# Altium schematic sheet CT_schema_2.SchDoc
size 451 x 443 mm
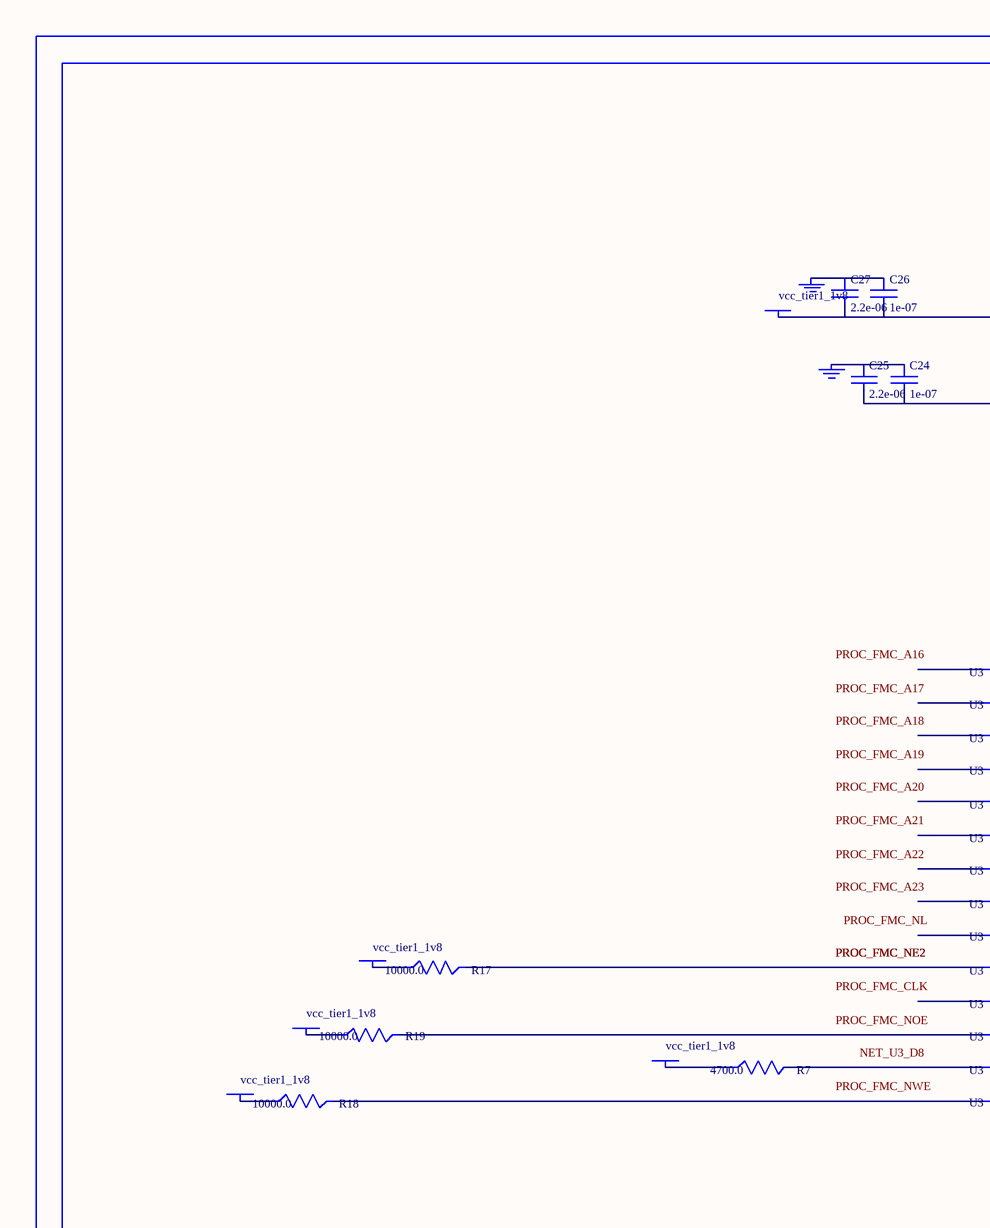
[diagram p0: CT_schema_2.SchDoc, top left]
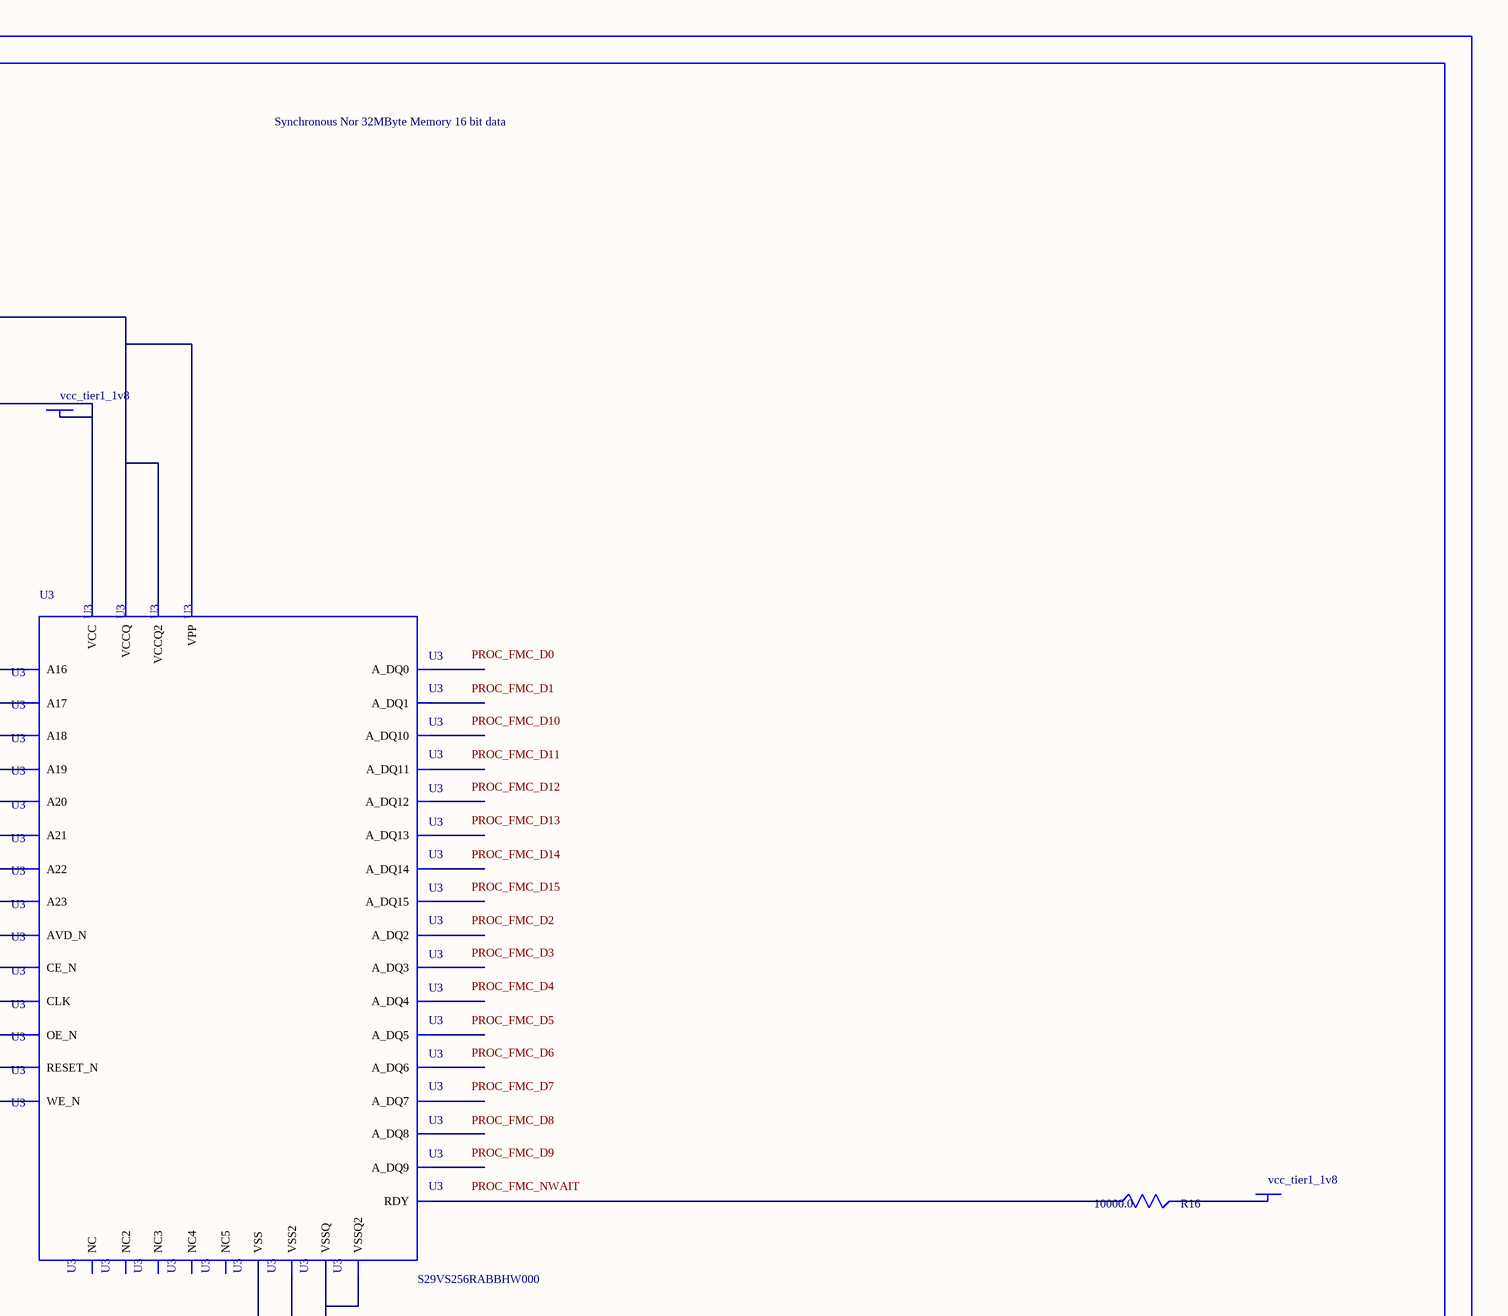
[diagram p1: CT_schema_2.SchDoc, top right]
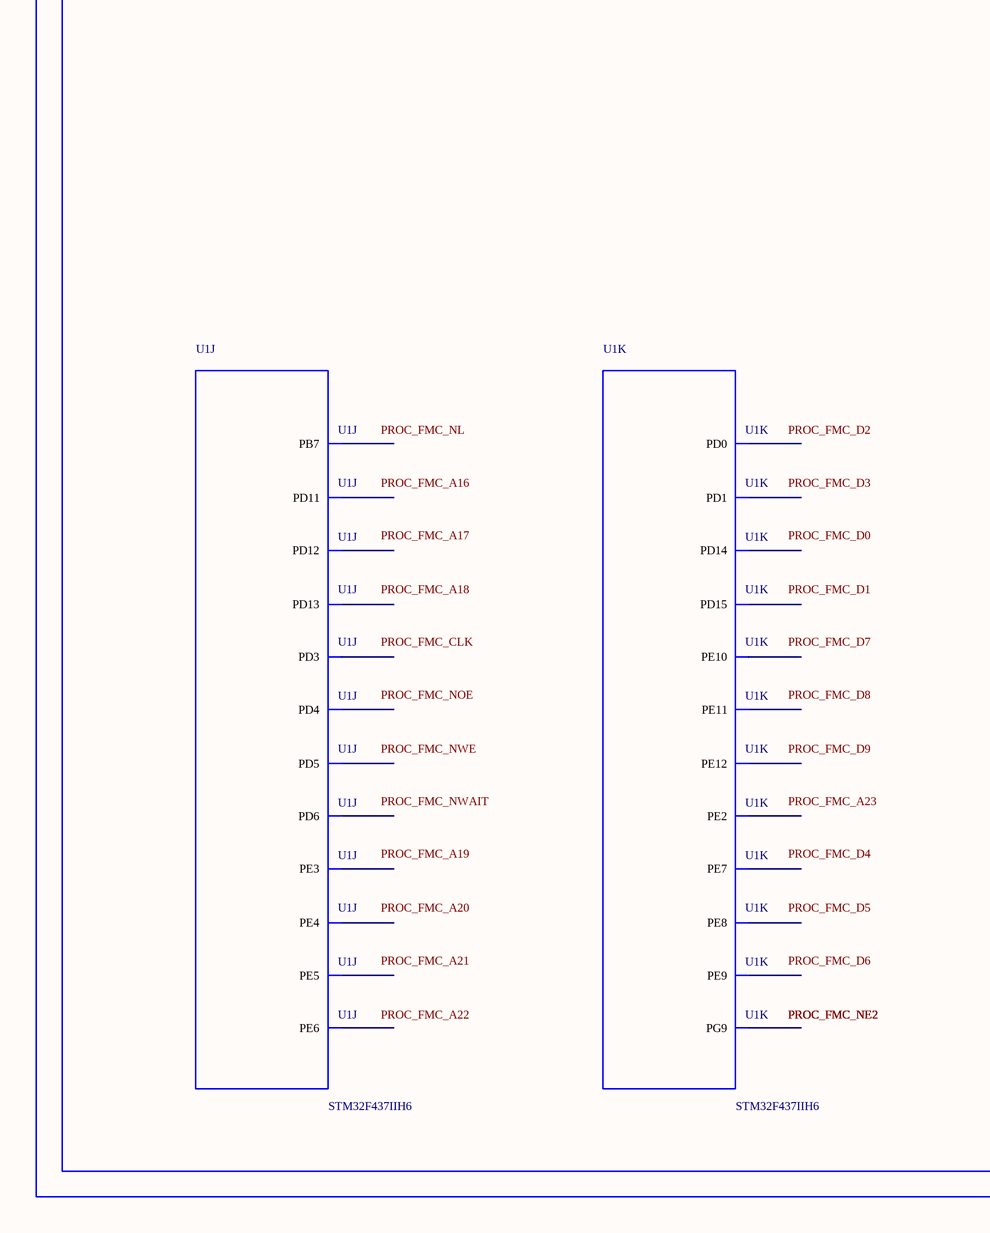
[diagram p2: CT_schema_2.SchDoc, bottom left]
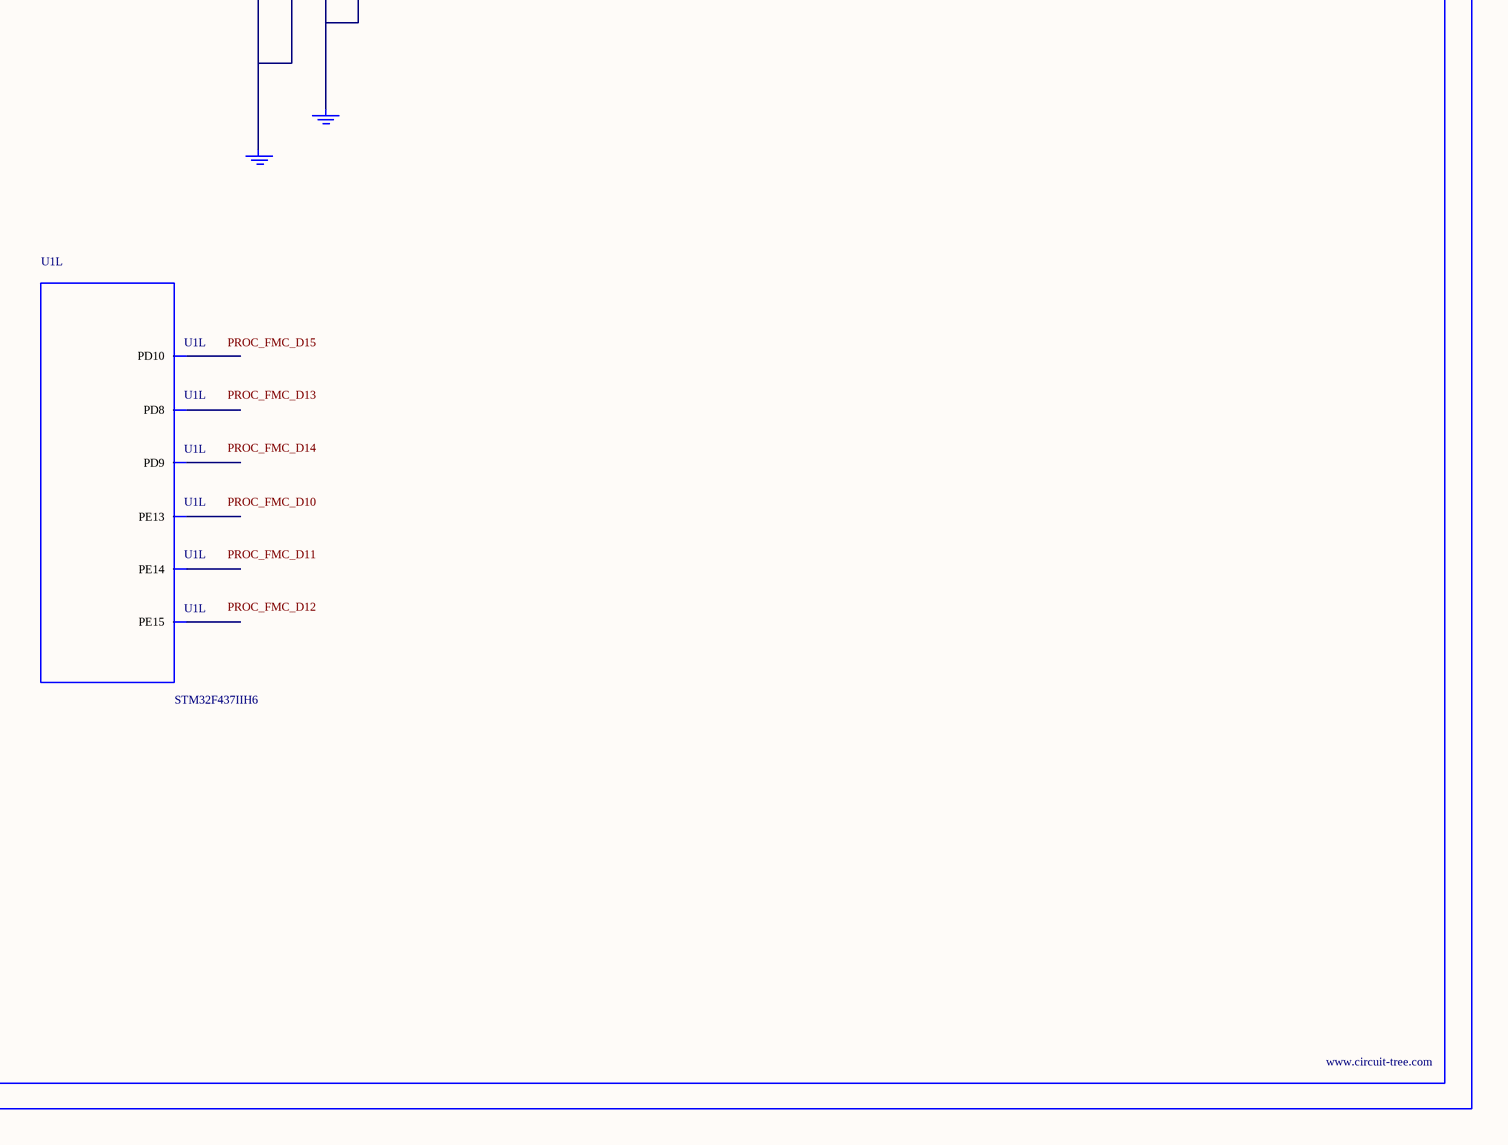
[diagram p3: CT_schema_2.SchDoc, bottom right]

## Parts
BORDER1  (no value)
C24  1e-07  [C0402]
C25  2.2e-06  [C0603]
C26  1e-07  [C0402]
C27  2.2e-06  [C0603]
GND_INSTANCE_1_0  (no value)
GND_INSTANCE_1_1  (no value)
GND_INSTANCE_1_2  (no value)
GND_INSTANCE_1_3  (no value)
POWER_INSTANCE_1_0  vcc_tier1_1v8
POWER_INSTANCE_1_1  vcc_tier1_1v8
POWER_INSTANCE_1_2  vcc_tier1_1v8
POWER_INSTANCE_1_3  vcc_tier1_1v8
POWER_INSTANCE_1_4  vcc_tier1_1v8
POWER_INSTANCE_1_5  vcc_tier1_1v8
POWER_INSTANCE_1_6  vcc_tier1_1v8
R7  4700.0  [R0603]
R16  10000.0  [R0603]
R17  10000.0  [R0603]
R18  10000.0  [R0603]
R19  10000.0  [R0603]
U1  STM32F437IIH6  [UFBGA176_25]  (parts J,K,L of 15)
U3  S29VS256RABBHW000  [S29VS256RABBHW000]

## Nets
NetC24_1: C24.1 C25.1 GND_INSTANCE_1_0.0(GND)
NetC24_2: C24.2 C25.2 POWER_INSTANCE_1_0.0(PWR) U3.C7(VCC)
NetC26_1: C26.1 C27.1 GND_INSTANCE_1_1.0(GND)
NetC26_2: C26.2 C27.2 POWER_INSTANCE_1_1.0(PWR) U3.C9(VPP) U3.D3(VCCQ) U3.F10(VCCQ2)
NetGND_INSTANCE_1_2_0: GND_INSTANCE_1_2.0(GND) U3.C5(VSS) U3.D12(VSS2)
NetGND_INSTANCE_1_3_0: GND_INSTANCE_1_3.0(GND) U3.E3(VSSQ) U3.F5(VSSQ2)
NetPOWER_INSTANCE_1_2_0: POWER_INSTANCE_1_2.0(PWR) R16.2
NetPOWER_INSTANCE_1_3_0: POWER_INSTANCE_1_3.0(PWR) R17.1
NetPOWER_INSTANCE_1_4_0: POWER_INSTANCE_1_4.0(PWR) R18.1
NetPOWER_INSTANCE_1_5_0: POWER_INSTANCE_1_5.0(PWR) R19.1
NetPOWER_INSTANCE_1_6_0: POWER_INSTANCE_1_6.0(PWR) R7.1
NetR7_2: R7.2 U3.D8(RESET_N)
NetR16_1: R16.1 U3.C3(RDY)
NetR17_2: R17.2 U3.D11(CE_N)
NetR18_2: R18.2 U3.C8(WE_N)
NetR19_2: R19.2 U3.E12(OE_N)

Not connected (* = marked no-connect by the designer): U1 A1(PE3) A2(PE2) B1(PE4) B2(PE5) B3(PE6) B5(PB7) B11(PD6) B12(PD0) C10(PG9) C11(PD5) C12(PD1) D10(PD4) D11(PD3) L14(PD15) M14(PD14) M15(PD13) N11(PE13) N13(PD12) N14(PD11) N15(PD10) P8(PE8) P9(PE9) P10(PE11) P11(PE14) P14(PD9) P15(PD8) R8(PE7) R9(PE10) R10(PE12) R11(PE15); U3 A1(NC) A14(NC2) C4(A21) C6(CLK) C10(A19) C11(A17) C12(A22) D4(A16) D5(A20) D6(AVD_N) D7(A23) D9(NC3) D10(A18) E4(A_DQ8) E5(A_DQ9) E6(A_DQ2) E7(A_DQ3) E8(A_DQ12) E9(A_DQ13) E10(A_DQ6) E11(A_DQ7) F3(A_DQ0) F4(A_DQ1) F6(A_DQ10) F7(A_DQ11) F8(A_DQ4) F9(A_DQ5) F11(A_DQ14) F12(A_DQ15) H1(NC4) H14(NC5)

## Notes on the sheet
- Labels drawn without touching a wire or pin: NET_U3_D8, PROC_FMC_A16, PROC_FMC_A17, PROC_FMC_A18, PROC_FMC_A19, PROC_FMC_A20, PROC_FMC_A21, PROC_FMC_A22, PROC_FMC_A23, PROC_FMC_CLK, PROC_FMC_D0, PROC_FMC_D1, PROC_FMC_D2, PROC_FMC_D3, PROC_FMC_D4, PROC_FMC_D5, PROC_FMC_D6, PROC_FMC_D7, PROC_FMC_D8, PROC_FMC_D9, PROC_FMC_D10, PROC_FMC_D11, PROC_FMC_D12, PROC_FMC_D13, PROC_FMC_D14, PROC_FMC_D15, PROC_FMC_NL, PROC_FMC_NOE, PROC_FMC_NWAIT, PROC_FMC_NWE

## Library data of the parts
BORDER1 = BORDER_PAGE1
C24 C26 = C0402C104K3RACTU
C25 C27 = C0603C225K8RACTU
GND_INSTANCE_1_0-GND_INSTANCE_1_3 = GND
POWER_INSTANCE_1_0-POWER_INSTANCE_1_6 = PWR
R7 = RC0603JR-074K7L
R16-R19 = RC0603JR-0710KL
